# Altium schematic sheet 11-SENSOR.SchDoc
size A4
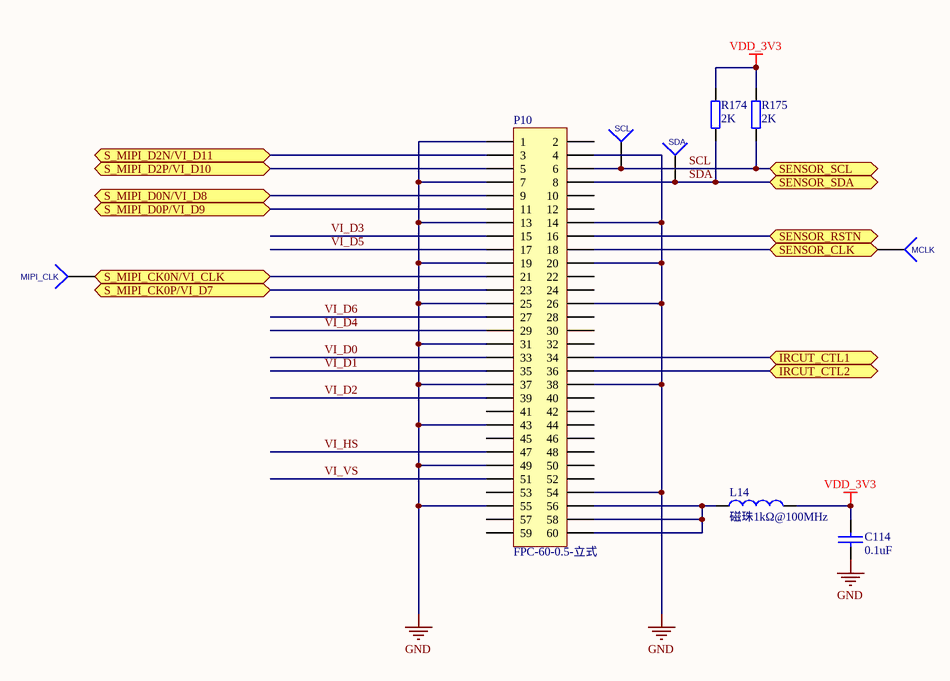
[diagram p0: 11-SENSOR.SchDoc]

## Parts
C114  0.1uF  [C0402]
L14  磁珠1kΩ@100MHz  [L0603]
MCLK  (no value)  [test]
MIPI_CLK  (no value)  [test]
P10  FPC-60-0.5-立式  [FPC-60-0.5-立式]
R174  2K  [R0402]
R175  2K  [R0402]
SCL  (no value)  [test]
SDA  (no value)  [test]

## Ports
IRCUT_CTL1 (bidir), IRCUT_CTL2 (bidir), S_MIPI_CK0N/VI_CLK (bidir), S_MIPI_CK0P/VI_D7 (bidir), S_MIPI_D0N/VI_D8 (bidir), S_MIPI_D0P/VI_D9 (bidir), S_MIPI_D2N/VI_D11 (bidir), S_MIPI_D2P/VI_D10 (bidir), SENSOR_CLK (bidir), SENSOR_RSTN (bidir), SENSOR_SCL (bidir), SENSOR_SDA (bidir)

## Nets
GND: C114.2 P10.1 P10.4 P10.7 P10.13 P10.14 P10.19 P10.20 P10.25 P10.26 P10.31 P10.37 P10.38 P10.43 P10.49 P10.54 P10.55
VDD_3V3: C114.1 L14.2 R174.2 R175.2
IRCUT_CTL1: P10.34 ; port IRCUT_CTL1
IRCUT_CTL2: P10.36 ; port IRCUT_CTL2
S_MIPI_CK0N/VI_CLK: MIPI_CLK.1(A) P10.21 ; port S_MIPI_CK0N/VI_CLK
S_MIPI_CK0P/VI_D7: P10.23 ; port S_MIPI_CK0P/VI_D7
S_MIPI_D0N/VI_D8: P10.9 ; port S_MIPI_D0N/VI_D8
S_MIPI_D0P/VI_D9: P10.11 ; port S_MIPI_D0P/VI_D9
S_MIPI_D2N/VI_D11: P10.3 ; port S_MIPI_D2N/VI_D11
S_MIPI_D2P/VI_D10: P10.5 ; port S_MIPI_D2P/VI_D10
SCL: P10.6 R175.1 SCL.1(A) ; port SENSOR_SCL
SDA: P10.8 R174.1 SDA.1(A) ; port SENSOR_SDA
SENSOR_CLK: MCLK.1(A) P10.18 ; port SENSOR_CLK
SENSOR_RSTN: P10.16 ; port SENSOR_RSTN
VI_D0: P10.33
VI_D1: P10.35
VI_D2: P10.39
VI_D3: P10.15
VI_D4: P10.29
VI_D5: P10.17
VI_D6: P10.27
VI_HS: P10.47
VI_VS: P10.51
NetL14_1: L14.1 P10.56 P10.58 P10.60

Not connected (* = marked no-connect by the designer): P10 2 10 12 22 24 28 30 32 40 41 42 44 45 46 48 50 52 53 57 59

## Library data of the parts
C114 = 电容: Capacitor
L14 = 电感: Inductor
MCLK MIPI_CLK SCL SDA = Test_Jack
P10 = Header 30X2: Header, 30-Pin, Dual row
R174 R175 = 电阻Ω: Resistor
